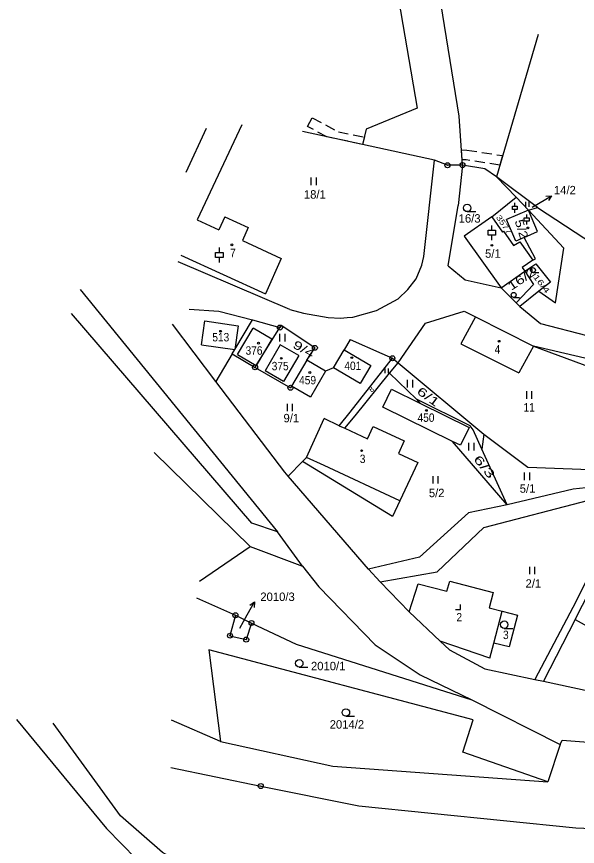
# Model space of a CAD drawing. Extents: x -665688 to -664583, y -1006118 to -1004927.
# Drawn here: x -665637.6 to -665524.4, y -1005201.6 to -1005034.2 of the extents above; entities that cross this region are included whole.
import ezdxf
from ezdxf.enums import TextEntityAlignment as Align

# ---------------------------------------------------------------- set-up
doc = ezdxf.new("R2010")
doc.units = 0
doc.header["$LTSCALE"] = 0.68
doc.linetypes.add('MEDIUM_DASHED', pattern=[4.5, 3, -1.5])
for name, color, linetype, lineweight in [('1', 7, 'Continuous', 25), ('16', 7, 'Continuous', 25), ('24', 7, 'Continuous', 25), ('25', 7, 'Continuous', 25), ('27', 7, 'MEDIUM_DASHED', 25), ('4', 7, 'Continuous', 25)]:
    doc.layers.add(name, color=color, linetype=linetype, lineweight=lineweight)
doc.layers.add('18', color=7, linetype='Continuous')
doc.layers.add('19', color=7, linetype='Continuous')

msp = doc.modelspace()

# ---------------------------------------------------------------- linework, layer by layer
at = {"layer": '1'}
for p, q in [((-665532.32, -1005037.79), (-665540.72, -1005066.52)), ((-665599.34, -1005056.73), (-665603.44, -1005065.67)), ((-665567.74, -1005060), (-665579.87, -1005057.36)), ((-665553.25, -1005063.16), (-665567.74, -1005060)), ((-665547.58, -1005064.14), (-665548.46, -1005072.32)), ((-665532.44, -1005072.72), (-665540.72, -1005066.52)), ((-665550.46, -1005084.49), (-665548.46, -1005072.32)), ((-665534.23, -1005073.27), (-665538.66, -1005075.12)), ((-665534.23, -1005073.27), (-665532.44, -1005072.72)), ((-665532.44, -1005072.72), (-665521.14, -1005080.12)), ((-665595.55, -1005074.55), (-665596.75, -1005077.18)), ((-665595.55, -1005074.55), (-665590.81, -1005076.74)), ((-665536.84, -1005079.48), (-665538.66, -1005075.12)), ((-665590.81, -1005076.74), (-665592, -1005079.37)), ((-665535.1, -1005078.76), (-665536.84, -1005079.48)), ((-665592, -1005079.37), (-665584.18, -1005082.97)), ((-665604.41, -1005082.35), (-665587.37, -1005090.1)), ((-665528.79, -1005091.93), (-665527.15, -1005080.93)), ((-665582.45, -1005093.28), (-665604.98, -1005083.69)), ((-665584.18, -1005082.97), (-665587.37, -1005090.1)), ((-665550.46, -1005084.49), (-665547.02, -1005087.31)), ((-665535.53, -1005084.83), (-665535.01, -1005085.57)), ((-665535.01, -1005085.57), (-665532.75, -1005084.09)), ((-665532.75, -1005084.09), (-665529.82, -1005087.76)), ((-665547.02, -1005087.31), (-665539.74, -1005088.94)), ((-665533.23, -1005088.22), (-665536.71, -1005091.93)), ((-665624.74, -1005089.28), (-665584.91, -1005138.14)), ((-665532.19, -1005089.6), (-665528.79, -1005091.93)), ((-665590.07, -1005136.42), (-665626.51, -1005094.06)), ((-665602.77, -1005093.23), (-665596.74, -1005093.65)), ((-665596.74, -1005093.65), (-665590, -1005095.4)), ((-665600.27, -1005100.39), (-665599.57, -1005095.6)), ((-665599.57, -1005095.6), (-665592.83, -1005096.58)), ((-665593.53, -1005101.37), (-665590, -1005095.4)), ((-665590, -1005095.4), (-665584.43, -1005096.93)), ((-665597.34, -1005107.82), (-665606.13, -1005096.24)), ((-665592.83, -1005096.58), (-665593.53, -1005101.37)), ((-665584.43, -1005096.93), (-665584.19, -1005096.54)), ((-665577.37, -1005101.02), (-665584.19, -1005096.54)), ((-665600.27, -1005100.39), (-665593.53, -1005101.37)), ((-665584.36, -1005100.38), (-665587.43, -1005105.65)), ((-665580.64, -1005102.55), (-665584.36, -1005100.38)), ((-665570.23, -1005099.31), (-665571.48, -1005101.44)), ((-665533.23, -1005100.65), (-665536.19, -1005106.05)), ((-665594.05, -1005102.23), (-665597.34, -1005107.82)), ((-665594.05, -1005102.23), (-665593.53, -1005101.37)), ((-665594.05, -1005102.23), (-665589.45, -1005104.96)), ((-665578.99, -1005103.51), (-665577.37, -1005101.02)), ((-665580.64, -1005102.55), (-665583.71, -1005107.82)), ((-665570.25, -1005114), (-665561.73, -1005103.12)), ((-665561.73, -1005103.12), (-665560.56, -1005104.02)), ((-665589.45, -1005104.96), (-665582.31, -1005109.08)), ((-665583.71, -1005107.82), (-665587.43, -1005105.65)), ((-665573.61, -1005105.07), (-665575.2, -1005105.72)), ((-665569.26, -1005114.72), (-665562.34, -1005106.13)), ((-665562.34, -1005106.13), (-665556.88, -1005111.4)), ((-665583.45, -1005126.11), (-665597.34, -1005107.82)), ((-665582.09, -1005108.78), (-665582.31, -1005109.08)), ((-665563.69, -1005113.02), (-665561.92, -1005109.37)), ((-665556.88, -1005111.4), (-665556.21, -1005112.18)), ((-665572.49, -1005116.73), (-665570.25, -1005114)), ((-665579.04, -1005123.13), (-665575.48, -1005115.3)), ((-665572.49, -1005116.73), (-665575.48, -1005115.3)), ((-665571.36, -1005117.26), (-665569.26, -1005114.72)), ((-665572.49, -1005116.73), (-665571.36, -1005117.26)), ((-665571.36, -1005117.26), (-665566.75, -1005119.4)), ((-665546.21, -1005117.1), (-665547.96, -1005120.69)), ((-665543.3, -1005118.41), (-665543.65, -1005121.45)), ((-665538.58, -1005132.69), (-665549.57, -1005119.91)), ((-665590.45, -1005141.12), (-665609.8, -1005122.12)), ((-665579.87, -1005123.98), (-665582.74, -1005126.93)), ((-665579.04, -1005123.13), (-665579.87, -1005123.98)), ((-665561.69, -1005135.04), (-665579.87, -1005123.98)), ((-665560.23, -1005131.91), (-665561.69, -1005135.04)), ((-665584.91, -1005138.14), (-665590.07, -1005136.42)), ((-665579.85, -1005145.1), (-665584.91, -1005138.14)), ((-665600.66, -1005148.07), (-665590.45, -1005141.12)), ((-665524.85, -1005155.81), (-665518.03, -1005142.52)), ((-665566.58, -1005145.69), (-665564.22, -1005148.26)), ((-665564.22, -1005148.26), (-665558.34, -1005154.32)), ((-665601.28, -1005151.49), (-665593.42, -1005154.98)), ((-665524.66, -1005152.15), (-665532.99, -1005167.94)), ((-665552.11, -1005160.21), (-665558.34, -1005154.32)), ((-665593.42, -1005154.98), (-665594.51, -1005159.11)), ((-665524.85, -1005155.81), (-665531.25, -1005168.29)), ((-665524.85, -1005155.81), (-665514.79, -1005161.53)), ((-665590.17, -1005156.55), (-665591.23, -1005159.89)), ((-665594.51, -1005159.11), (-665591.23, -1005159.89)), ((-665565.22, -1005160.98), (-665556.09, -1005167)), ((-665542.09, -1005163.61), (-665552.11, -1005160.21)), ((-665538.17, -1005161.38), (-665541.22, -1005160.61)), ((-665543.04, -1005165.76), (-665532.99, -1005167.94)), ((-665556.09, -1005167), (-665545.66, -1005172.05)), ((-665532.99, -1005167.94), (-665531.25, -1005168.29)), ((-665596.46, -1005180.47), (-665606.33, -1005176.12))]:
    msp.add_line(p, q, dxfattribs=at)
for points in [[(-665557.92, -1004927.31), (-665555.11, -1004930.72), (-665560.8, -1004945.13), (-665565.17, -1004959.97), (-665566.63, -1004974.13), (-665562.99, -1005016.05), (-665556.74, -1005052.64), (-665567.04, -1005056.91), (-665567.74, -1005060)], [(-665547.58, -1005064.14), (-665548.25, -1005054.26), (-665556.32, -1005004.3)], [(-665592.09, -1005055.99), (-665601.14, -1005075.16), (-665596.75, -1005077.18)], [(-665582.45, -1005093.28), (-665579.7, -1005094.01), (-665574.7, -1005094.91), (-665572.2, -1005095.01), (-665570.87, -1005094.87), (-665569.7, -1005094.8), (-665564.96, -1005093.47), (-665560.59, -1005091.16), (-665558.59, -1005089.24), (-665556.92, -1005087.09), (-665555.81, -1005084.32), (-665555.37, -1005082.62), (-665553.25, -1005063.16)], [(-665547.58, -1005064.14), (-665550.61, -1005064.18), (-665553.25, -1005063.16)], [(-665540.72, -1005066.52), (-665543.08, -1005064.87), (-665547.58, -1005064.14)], [(-665541.68, -1005074.58), (-665536.75, -1005070.64), (-665540.72, -1005066.52)], [(-665527.15, -1005080.93), (-665534.23, -1005073.27), (-665536.75, -1005070.64)], [(-665541.68, -1005074.58), (-665547.26, -1005078.5), (-665539.74, -1005088.94)], [(-665541.68, -1005074.58), (-665539.52, -1005077.65), (-665539.29, -1005077.49)], [(-665539.29, -1005077.49), (-665537.27, -1005080.37), (-665536, -1005079.61), (-665533.37, -1005083.31), (-665535.53, -1005084.83)], [(-665533.37, -1005083.31), (-665532.81, -1005083.05), (-665535.1, -1005078.76)], [(-665539.74, -1005088.94), (-665535.01, -1005085.57), (-665533.23, -1005088.22)], [(-665535.98, -1005092.65), (-665536.71, -1005091.93), (-665539.74, -1005088.94)], [(-665529.82, -1005087.76), (-665532.19, -1005089.6), (-665535.98, -1005092.65)], [(-665560.56, -1005104.02), (-665555.06, -1005096.04), (-665547.27, -1005093.64)], [(-665547.27, -1005093.64), (-665544.94, -1005094.79), (-665547.9, -1005100.19), (-665536.19, -1005106.05)], [(-665535.98, -1005092.65), (-665531.82, -1005096.14), (-665503.75, -1005103.38)], [(-665544.94, -1005094.79), (-665533.23, -1005100.65), (-665505.02, -1005111.13), (-665511.14, -1005125.96)], [(-665589.45, -1005104.96), (-665589.24, -1005104.61), (-665584.43, -1005096.93)], [(-665570.23, -1005099.31), (-665563.89, -1005102.16), (-665561.73, -1005103.12)], [(-665505.02, -1005111.13), (-665503.92, -1005107.53), (-665533.23, -1005100.65)], [(-665575.2, -1005105.72), (-665578.99, -1005103.51), (-665582.09, -1005108.78)], [(-665562.34, -1005106.13), (-665560.56, -1005104.02), (-665543.3, -1005118.41)], [(-665575.2, -1005105.72), (-665578.29, -1005110.97), (-665582.09, -1005108.78)], [(-665561.92, -1005109.37), (-665556.21, -1005112.18), (-665546.21, -1005117.1)], [(-665538.58, -1005132.69), (-665543.65, -1005121.45), (-665545.39, -1005117.59), (-665546.05, -1005116.79), (-665556.88, -1005111.4)], [(-665547.96, -1005120.69), (-665549.57, -1005119.91), (-665563.69, -1005113.02)], [(-665566.75, -1005119.4), (-665565.59, -1005116.9), (-665559.35, -1005119.8), (-665560.52, -1005122.31), (-665556.61, -1005124.13), (-665560.23, -1005131.91)], [(-665543.3, -1005118.41), (-665534.37, -1005125.08), (-665511.14, -1005125.96), (-665514.04, -1005132.26), (-665520.11, -1005128.99), (-665525.24, -1005129.57), (-665538.58, -1005132.69)], [(-665566.58, -1005145.69), (-665582.74, -1005126.93), (-665583.45, -1005126.11)], [(-665564.22, -1005148.26), (-665552.71, -1005146.21), (-665543.25, -1005137.26), (-665522.06, -1005131.79), (-665516.57, -1005135.18)], [(-665538.58, -1005132.69), (-665546.36, -1005134.32), (-665556.25, -1005143.26), (-665566.58, -1005145.69)], [(-665516.57, -1005135.18), (-665519.49, -1005141.81), (-665524.66, -1005152.15)], [(-665590.45, -1005141.12), (-665579.85, -1005145.1), (-665576.61, -1005149.22), (-665565.22, -1005160.98)], [(-665558.34, -1005154.32), (-665556.55, -1005148.64), (-665550.74, -1005150.12), (-665550.16, -1005148.12), (-665541.38, -1005150.41), (-665542.22, -1005153.46), (-665539.54, -1005154.14)], [(-665542.09, -1005163.61), (-665541.22, -1005160.61), (-665539.54, -1005154.14)], [(-665539.54, -1005154.14), (-665536.47, -1005154.99), (-665538.17, -1005161.38)], [(-665593.42, -1005154.98), (-665590.17, -1005156.55), (-665581.14, -1005160.82), (-665545.66, -1005172.05), (-665527.86, -1005181.07), (-665527.45, -1005180.2), (-665515.99, -1005181.03), (-665490.32, -1005183.42), (-665458.39, -1005187.75), (-665437.98, -1005192.49), (-665417.3, -1005200.53), (-665399.75, -1005208.35)], [(-665552.11, -1005160.21), (-665550.2, -1005161.93), (-665543.04, -1005165.76)], [(-665527.86, -1005181.07), (-665530.34, -1005188.59), (-665547.48, -1005182.58), (-665545.43, -1005176.08), (-665598.78, -1005161.97), (-665596.46, -1005180.47), (-665573.78, -1005185.46), (-665530.34, -1005188.59)], [(-665531.25, -1005168.29), (-665510.97, -1005172.68), (-665505.84, -1005173.21)], [(-665637.59, -1005176.03), (-665619.42, -1005197.98), (-665610.34, -1005207.28), (-665593.31, -1005215.14), (-665581.94, -1005219.27)], [(-665429.85, -1005311.87), (-665474.09, -1005270.9), (-665483.93, -1005263.19), (-665503.85, -1005250.35), (-665521.76, -1005239.72), (-665538.2, -1005231.14), (-665560.7, -1005220.99), (-665592.26, -1005211.56), (-665608.15, -1005202.85), (-665616.64, -1005195.48), (-665630.18, -1005176.74)], [(-665606.44, -1005185.69), (-665588.29, -1005189.45), (-665568.47, -1005193.44), (-665524.68, -1005197.88), (-665491.46, -1005199.28), (-665463.07, -1005202.62), (-665454.32, -1005206.34), (-665437.29, -1005211.76), (-665406.05, -1005224.73)]]:
    msp.add_lwpolyline(points, dxfattribs=at)
msp.add_lwpolyline([(-665568.23, -1005108.23), (-665573.61, -1005105.07), (-665571.48, -1005101.44), (-665566.1, -1005104.57)], close=True, dxfattribs=at)
at = {"layer": '16'}
for p, q in [((-665532.22, -1005071.86), (-665529.622, -1005070.36)), ((-665533.51, -1005072.61), (-665532.22, -1005071.86)), ((-665591.06, -1005154.92), (-665589.592, -1005152.304)), ((-665592.54, -1005157.56), (-665591.06, -1005154.92))]:
    msp.add_line(p, q, dxfattribs=at)
for points in [[(-665530.738, -1005070.427), (-665529.622, -1005070.36), (-665530.238, -1005071.294)], [(-665590.518, -1005152.932), (-665589.592, -1005152.304), (-665589.646, -1005153.421)]]:
    msp.add_lwpolyline(points, dxfattribs=at)
at = {"layer": '24'}
for centre, radius in [((-665550.61, -1005064.18), 0.5), ((-665547.58, -1005064.14), 0.5), ((-665550.61, -1005064.18), 0.032), ((-665547.58, -1005064.14), 0.032), ((-665584.43, -1005096.93), 0.5), ((-665584.43, -1005096.93), 0.032), ((-665577.37, -1005101.02), 0.5), ((-665577.37, -1005101.02), 0.032), ((-665561.73, -1005103.12), 0.5), ((-665561.73, -1005103.12), 0.032), ((-665589.45, -1005104.96), 0.5), ((-665589.45, -1005104.96), 0.032), ((-665582.31, -1005109.08), 0.5), ((-665582.31, -1005109.08), 0.032), ((-665593.42, -1005154.98), 0.5), ((-665593.42, -1005154.98), 0.032), ((-665590.17, -1005156.55), 0.5), ((-665590.17, -1005156.55), 0.032), ((-665594.51, -1005159.11), 0.5), ((-665594.51, -1005159.11), 0.032), ((-665591.23, -1005159.89), 0.5), ((-665591.23, -1005159.89), 0.032), ((-665588.29, -1005189.45), 0.5), ((-665588.29, -1005189.45), 0.032)]:
    msp.add_circle(centre, radius, dxfattribs=at)
at = {"layer": '25'}
for p, q in [((-665578.097, -1005068.175), (-665578.097, -1005066.675)), ((-665577.063, -1005068.175), (-665577.063, -1005066.675)), ((-665537.01, -1005072.409), (-665537.01, -1005071.739)), ((-665534.796, -1005072.592), (-665534.796, -1005071.587)), ((-665534.103, -1005072.592), (-665534.103, -1005071.587)), ((-665546.62, -1005073.54), (-665544.87, -1005073.54)), ((-665537.01, -1005073.75), (-665537.01, -1005073.079)), ((-665534.6, -1005074.769), (-665534.6, -1005074.099)), ((-665534.6, -1005076.11), (-665534.6, -1005075.439)), ((-665541.64, -1005077.3), (-665541.64, -1005076.3)), ((-665541.64, -1005079.3), (-665541.64, -1005078.3)), ((-665596.66, -1005081.78), (-665596.66, -1005080.78)), ((-665596.66, -1005083.78), (-665596.66, -1005082.78)), ((-665533.34, -1005085.84), (-665532.167, -1005085.84)), ((-665537.25, -1005090.85), (-665536.077, -1005090.85)), ((-665584.417, -1005099.715), (-665584.417, -1005098.215)), ((-665583.383, -1005099.715), (-665583.383, -1005098.215)), ((-665563.186, -1005106.162), (-665563.186, -1005105.157)), ((-665562.493, -1005106.162), (-665562.493, -1005105.157)), ((-665558.657, -1005109.005), (-665558.657, -1005107.505)), ((-665557.623, -1005109.005), (-665557.623, -1005107.505)), ((-665534.587, -1005111.285), (-665534.587, -1005109.785)), ((-665533.553, -1005111.285), (-665533.553, -1005109.785)), ((-665582.927, -1005113.785), (-665582.927, -1005112.285)), ((-665581.893, -1005113.785), (-665581.893, -1005112.285)), ((-665546.277, -1005121.705), (-665546.277, -1005120.205)), ((-665545.243, -1005121.705), (-665545.243, -1005120.205)), ((-665553.507, -1005128.415), (-665553.507, -1005126.915)), ((-665552.473, -1005128.415), (-665552.473, -1005126.915)), ((-665535.047, -1005127.705), (-665535.047, -1005126.205)), ((-665534.013, -1005127.705), (-665534.013, -1005126.205)), ((-665533.987, -1005146.685), (-665533.987, -1005145.185)), ((-665532.953, -1005146.685), (-665532.953, -1005145.185)), ((-665539.15, -1005157.63), (-665537.4, -1005157.63)), ((-665580.53, -1005165.43), (-665578.78, -1005165.43)), ((-665571.11, -1005175.36), (-665569.36, -1005175.36))]:
    msp.add_line(p, q, dxfattribs=at)
for points in [[(-665536.507, -1005073.079), (-665537.512, -1005073.079), (-665537.512, -1005072.409), (-665536.507, -1005072.409)], [(-665534.097, -1005075.439), (-665535.102, -1005075.439), (-665535.102, -1005074.769), (-665534.097, -1005074.769)], [(-665540.89, -1005078.3), (-665542.39, -1005078.3), (-665542.39, -1005077.3), (-665540.89, -1005077.3)], [(-665595.91, -1005082.78), (-665597.41, -1005082.78), (-665597.41, -1005081.78), (-665595.91, -1005081.78)]]:
    msp.add_lwpolyline(points, close=True, dxfattribs=at)
msp.add_lwpolyline([(-665548.99, -1005153.82), (-665547.99, -1005153.82), (-665547.99, -1005152.82)], dxfattribs=at)
for centre, radius in [((-665546.62, -1005072.79), 0.75), ((-665534.37, -1005076.82), 0.175), ((-665594.13, -1005080.24), 0.175), ((-665541.64, -1005080.34), 0.175), ((-665533.3395, -1005085.3375), 0.5025), ((-665537.2495, -1005090.3475), 0.5025), ((-665596.41, -1005097.67), 0.175), ((-665588.76, -1005100.08), 0.175), ((-665540.18, -1005099.68), 0.175), ((-665584.15, -1005103.13), 0.175), ((-665569.92, -1005103), 0.175), ((-665578.4, -1005105.99), 0.175), ((-665554.86, -1005113.65), 0.175), ((-665567.94, -1005121.77), 0.175), ((-665539.15, -1005156.88), 0.75), ((-665580.53, -1005164.68), 0.75), ((-665571.11, -1005174.61), 0.75)]:
    msp.add_circle(centre, radius, dxfattribs=at)
at = {"layer": '27'}
for p, q in [((-665547.65, -1005063.08), (-665547.79, -1005061.08)), ((-665547.79, -1005061.08), (-665546.67, -1005061.1))]:
    msp.add_line(p, q, dxfattribs=at)
for points in [[(-665578.84, -1005056.38), (-665577.9, -1005054.61), (-665572.63, -1005057.41), (-665567.39, -1005058.47)], [(-665567.39, -1005058.47), (-665567.74, -1005060), (-665574.98, -1005058.42), (-665578.84, -1005056.38)], [(-665546.67, -1005061.1), (-665539.47, -1005062.24), (-665540.03, -1005064.16)], [(-665540.03, -1005064.16), (-665546.84, -1005063.09), (-665547.65, -1005063.08)]]:
    msp.add_lwpolyline(points, dxfattribs=at)
at = {"layer": '4'}
for p, q in [((-665592.98, -1005102.39), (-665589.84, -1005097.08)), ((-665586.09, -1005099.3), (-665589.84, -1005097.08)), ((-665586.09, -1005099.3), (-665589.24, -1005104.61)), ((-665592.98, -1005102.39), (-665589.24, -1005104.61)), ((-665575.5, -1005124.77), (-665579.04, -1005123.13)), ((-665560.23, -1005131.91), (-665575.5, -1005124.77))]:
    msp.add_line(p, q, dxfattribs=at)
msp.add_lwpolyline([(-665535.1, -1005078.76), (-665532.45, -1005077.53), (-665534.23, -1005073.27)], dxfattribs=at)

# ---------------------------------------------------------------- texts
at = {"layer": '16'}
for s, p in [('14/2', (-665529.12, -1005070.04)), ('2010/3', (-665588.39, -1005152.1))]:
    msp.add_text(s, height=1.7, dxfattribs=at).set_placement(p)
at = {"layer": '18'}
for s, height, p in [('18/1', 1.7, (-665577.3795, -1005070.91)), ('14/2', 0.1, (-665533.31, -1005072.41)), ('16/3', 1.7, (-665546.1395, -1005075.75)), ('9/1', 1.7, (-665582.1295, -1005116.05)), ('5/1', 1.7, (-665534.4395, -1005130.26)), ('5/2', 1.7, (-665552.7895, -1005131.15)), ('2/1', 1.7, (-665533.2695, -1005149.42)), ('2010/3', 0.1, (-665592.3395, -1005157.36)), ('2010/1', 1.7, (-665574.6895, -1005166.08)), ('2014/2', 1.7, (-665570.9095, -1005177.86))]:
    msp.add_text(s, height=height, dxfattribs=at).set_placement(p, align=Align.CENTER)
for s, height, rotation, width, p in [('3577', 1.14, 304.002, 1.25, (-665539.6734, -1005076.4652)), ('16/2', 1.7, 34.2, 1.4, (-665535.1608, -1005087.8003)), ('16/4', 1.14, 307.702, 1.45, (-665532.0703, -1005088.4274)), ('9/4', 1.7, 330.003, 1.45, (-665580.0285, -1005102.0162)), ('8', 1.14, 37.8, 0.85, (-665565.6468, -1005109.8192)), ('6/1', 1.7, 323.903, 1.55, (-665554.9758, -1005111.5554)), ('6/3', 1.7, 308.902, 1.65, (-665543.8202, -1005125.5497))]:
    msp.add_text(s, height=height, rotation=rotation, dxfattribs=dict(at, width=width)).set_placement(p, align=Align.CENTER)
at = {"layer": '18', "width": 0.9}
for s, p in [('11', (-665534.13, -1005113.87)), ('3', (-665538.8295, -1005159.79))]:
    msp.add_text(s, height=1.7, dxfattribs=at).set_placement(p, align=Align.CENTER)
at = {"layer": '19', "width": 1.25}
msp.add_text('5/2', height=1.7, rotation=287.402, dxfattribs=at).set_placement((-665536.4661, -1005077.3158), align=Align.CENTER)
at = {"layer": '19', "width": 0.9}
for s, p in [('7', (-665593.9295, -1005082.74)), ('513', (-665596.3695, -1005099.72)), ('376', (-665589.6595, -1005102.41)), ('4', (-665540.5195, -1005102.17)), ('375', (-665584.3795, -1005105.55)), ('401', (-665569.7195, -1005105.5)), ('459', (-665578.8495, -1005108.39)), ('450', (-665554.9395, -1005115.95)), ('3', (-665567.7395, -1005124.27)), ('2', (-665548.2295, -1005156.22))]:
    msp.add_text(s, height=1.7, dxfattribs=at).set_placement(p, align=Align.CENTER)
at = {"layer": '19'}
msp.add_text('5/1', height=1.7, dxfattribs=at).set_placement((-665541.4395, -1005082.84), align=Align.CENTER)

doc.saveas('drawing.dxf')
